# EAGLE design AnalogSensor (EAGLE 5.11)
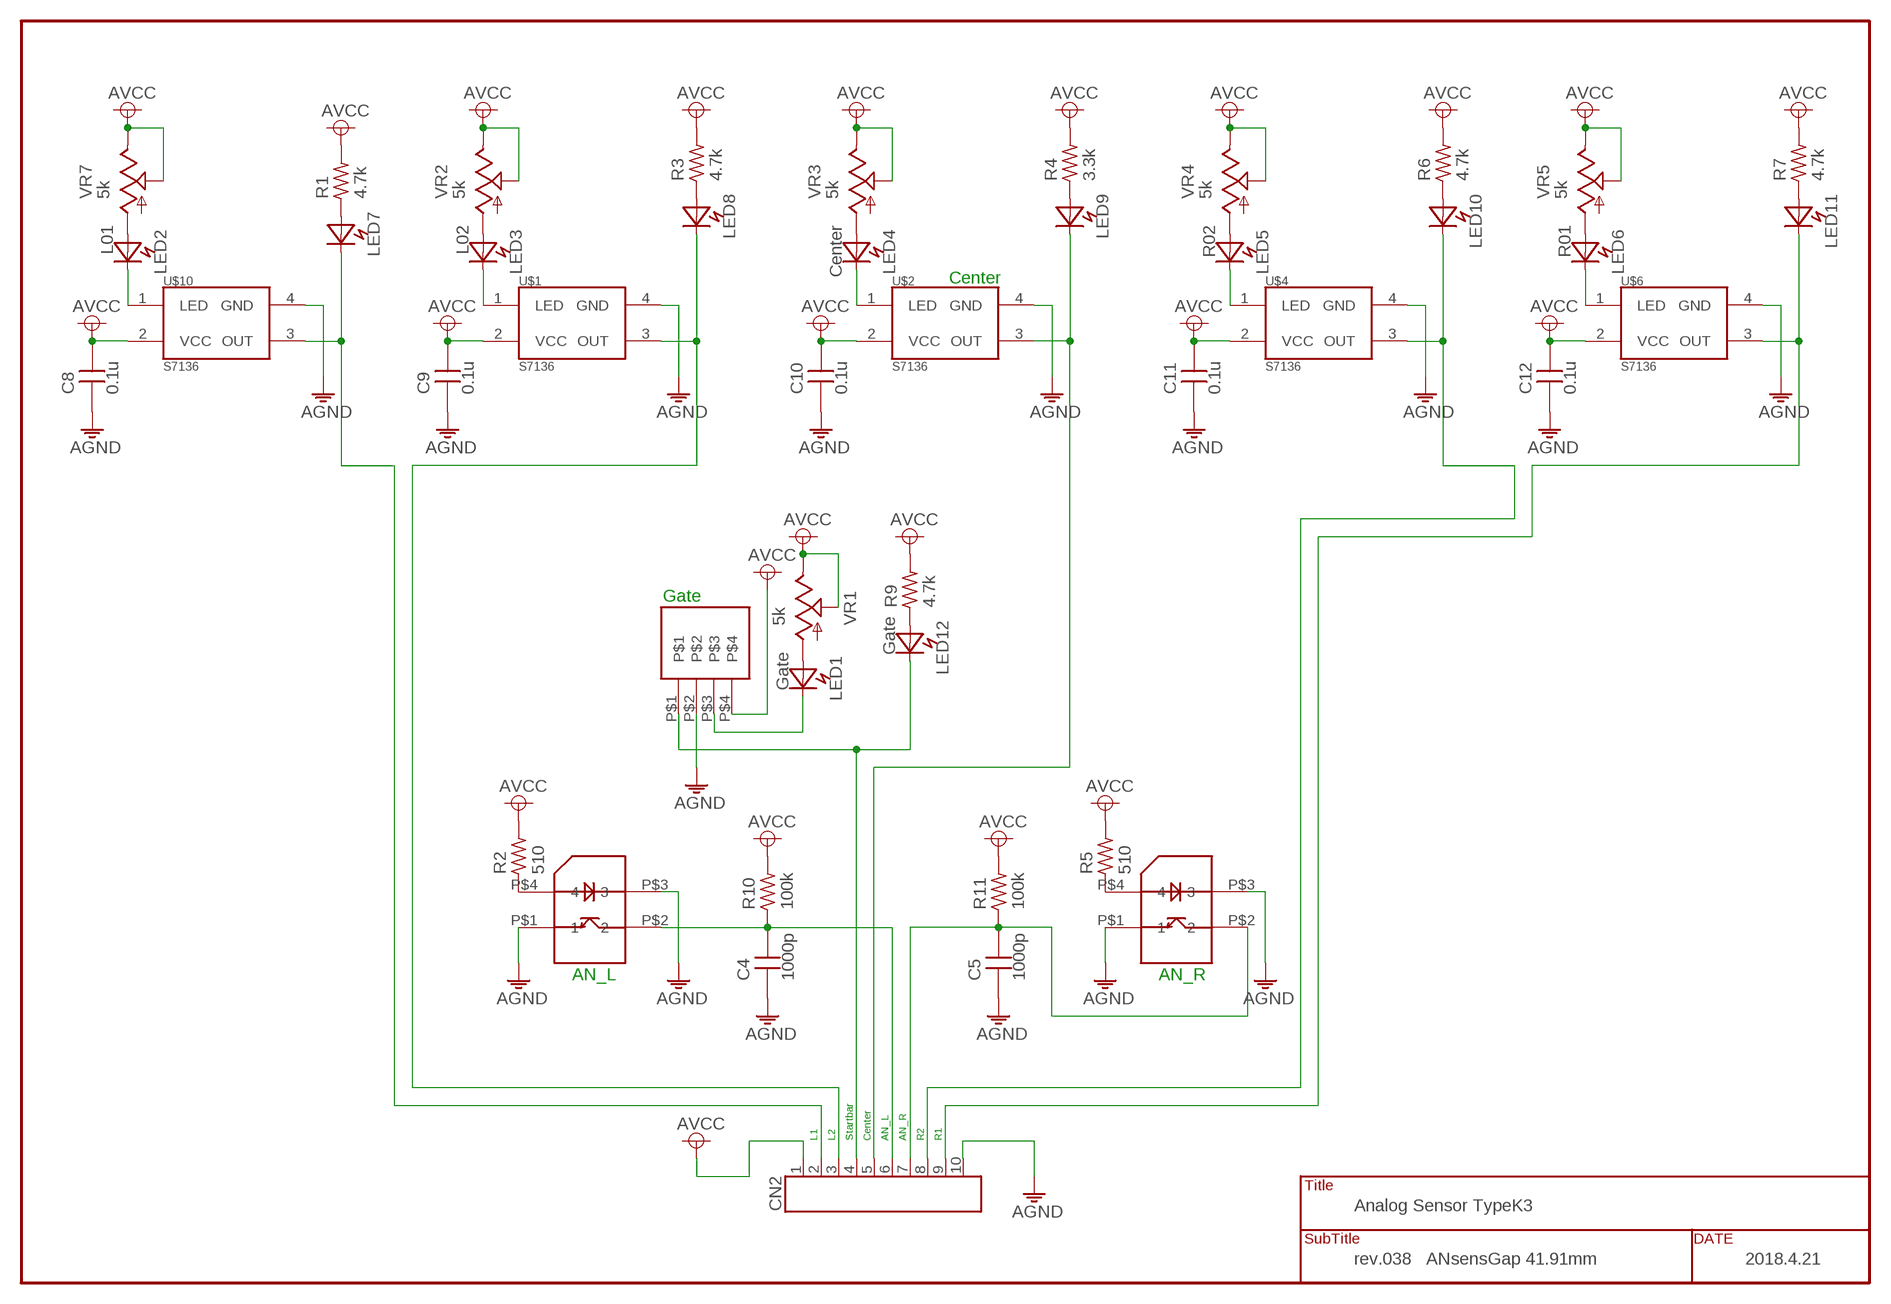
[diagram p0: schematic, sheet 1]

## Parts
C4  1000p  CAP1608RC  [1608]
C5  1000p  CAP1608RC  [1608]
C8  0.1u  CAPSM1608  [C1608]
C9  0.1u  CAPSM1608  [C1608]
C10  0.1u  CAPSM1608  [C1608]
C11  0.1u  CAPSM1608  [C1608]
C12  0.1u  CAPSM1608  [C1608]
CN2  CON_10P-0.8N  [10P-0.8N]
LED1  Gate  LED-0.9  [LED_3MM]
LED2  L01  LED-0.9  [LED_3MM]
LED3  L02  LED-0.9  [LED_3MM]
LED4  Center  LED-0.9  [LED_3MM]
LED5  R02  LED-0.9  [LED_3MM]
LED6  R01  LED-0.9  [LED_3MM]
LED7  LED-1608C  [LED_1608C]
LED8  LED-1608C  [LED_1608C]
LED9  LED-1608C  [LED_1608C]
LED10  LED-1608C  [LED_1608C]
LED11  LED-1608C  [LED_1608C]
LED12  Gate  LED-1608C  [LED_1608C]
R1  4.7k  R1608C  [C1608C]
R2  510  R1608RC  [1608]
R3  4.7k  R1608C  [C1608C]
R4  3.3k  R1608C  [C1608C]
R5  510  R1608RC  [1608]
R6  4.7k  R1608C  [C1608C]
R7  4.7k  R1608C  [C1608C]
R9  4.7k  R1608C  [C1608C]
R10  100k  R1608RC  [1608]
R11  100k  R1608RC  [1608]
U$1  S7136  S7136-0.9  [S7136]
U$2  S7136  S7136-0.9  [S7136]
U$3  GP2S700HCP  GP2S700HCP-SMD  [GP2S700HCP]
U$4  S7136  S7136-0.9  [S7136]
U$6  S7136  S7136-0.9  [S7136]
U$7  GP2S700HCP  GP2S700HCP-SMD  [GP2S700HCP]
U$10  S7136  S7136-0.9  [S7136]
U$15  S6846-SMD  [S6846-SMD]
VR1  5k  POTSMD  [ST-4EB]
VR2  5k  POTSMD  [ST-4EB]
VR3  5k  POTSMD  [ST-4EB]
VR4  5k  POTSMD  [ST-4EB]
VR5  5k  POTSMD  [ST-4EB]
VR7  5k  POTSMD  [ST-4EB]

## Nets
AGND: C4.1 C5.1 C8.1 C9.1 C10.1 C11.1 C12.1 CN2.10 U$1.4(GND) U$2.4(GND) U$3.P$1 U$3.P$3 U$4.4(GND) U$6.4(GND) U$7.P$1 U$7.P$3 U$10.4(GND) U$15.P$2
AN_L: C4.2 CN2.6 R10.1 U$7.P$2
AN_R: C5.2 CN2.7 R11.1 U$3.P$2
AVCC: C8.2 C9.2 C10.2 C11.2 C12.2 CN2.1 R1.2 R2.2 R3.2 R4.2 R5.2 R6.2 R7.2 R9.2 R10.2 R11.2 U$1.2(VCC) U$2.2(VCC) U$4.2(VCC) U$6.2(VCC) U$10.2(VCC) U$15.P$4 VR1.P$2(S) VR1.P$3(E) VR2.P$2(S) VR2.P$3(E) VR3.P$2(S) VR3.P$3(E) VR4.P$2(S) VR4.P$3(E) VR5.P$2(S) VR5.P$3(E) VR7.P$2(S) VR7.P$3(E)
CENTER: CN2.5 LED9.K U$2.3(OUT)
L1: CN2.2 LED7.K U$10.3(OUT)
L2: CN2.3 LED8.K U$1.3(OUT)
N$1: LED3.K U$1.1(LED)
N$2: LED1.A VR1.P$1(A)
N$3: LED3.A VR2.P$1(A)
N$4: R2.1 U$7.P$4
N$5: R5.1 U$3.P$4
N$7: LED4.K U$2.1(LED)
N$11: LED7.A R1.1
N$12: LED8.A R3.1
N$13: LED4.A VR3.P$1(A)
N$14: LED9.A R4.1
N$15: LED1.K U$15.P$3
N$17: LED10.A R6.1
N$18: LED11.A R7.1
N$19: LED5.K U$4.1(LED)
N$20: LED2.K U$10.1(LED)
N$21: LED12.A R9.1
N$23: LED2.A VR7.P$1(A)
N$24: LED5.A VR4.P$1(A)
N$27: LED6.K U$6.1(LED)
N$30: LED6.A VR5.P$1(A)
R1: CN2.9 LED11.K U$6.3(OUT)
R2: CN2.8 LED10.K U$4.3(OUT)
STARTBAR: CN2.4 LED12.K U$15.P$1

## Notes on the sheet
- Center
- Gate
- AN_L | AN_R
- L1 | L2 | Startbar | Center | AN_L | AN_R | R2 | R1
- Analog Sensor TypeK3
- rev.038   ANsensGap 41.91mm | 2018.4.21

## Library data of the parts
C4 C5 C8-C12 = _mylib02:CAP: Non polar capacitor
CN2 = _mylib02:CON_10P: 10P Molex Connector
LED1-LED12 = _mylib02:LED: 3mm LED
R1-R7 R9-R11 = _mylib02:R: General Resiter 1/8W 1/4W 1/2W V/H
U$1 U$2 U$4 U$6 U$10 = _mylib02:S7136
U$3 U$7 = _mylib02:GP2S700HCP
U$15 = _mylib02:S6846
VR1-VR5 VR7 = _mylib02:POT: Volume Trimmer Resister

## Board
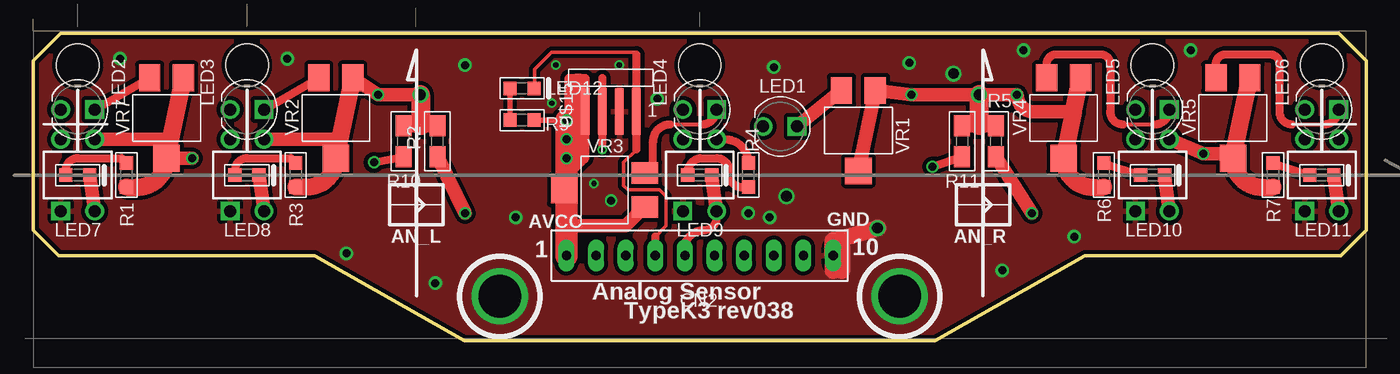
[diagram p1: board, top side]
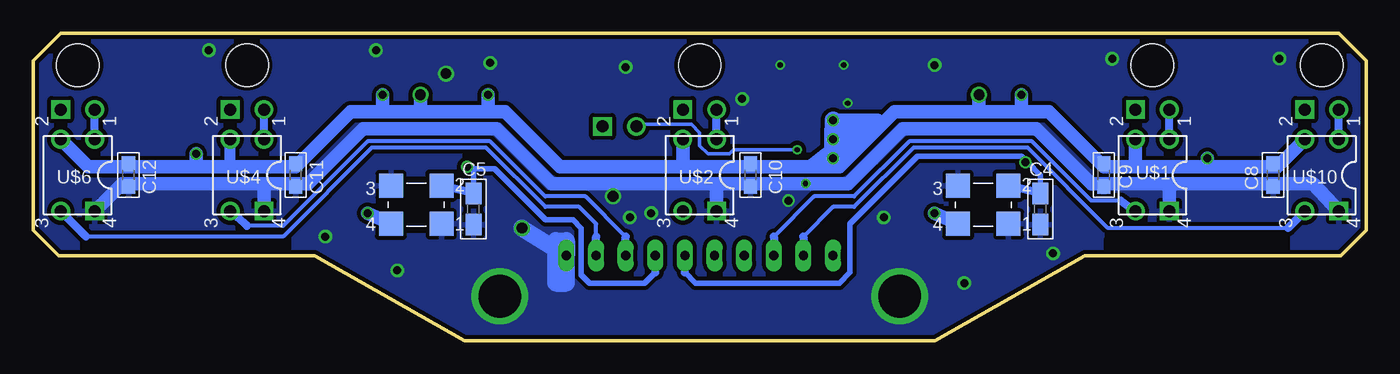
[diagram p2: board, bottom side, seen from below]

Size 100.01 x 23.04 mm. Coordinates in mm from the lower left corner, seen from the top.
Outline: 1.91,6.37 21.11,6.37 32.35,0 67.66,0 78.9,6.37 98.11,6.37 100.01,8.28 100.01,20.98 97.95,23.04 2.06,23.04 0,20.98 0,8.28 1.91,6.37
Copper layers (1*16): Top 0.035mm / dielectric 1.5mm / Bottom 0.035mm
Design rules "Fusion_eagle_rule_v1.1": minimum track width 6mil, minimum drill 12mil, track to track 6mil, track to pad 6mil, pad to pad 6mil, via to via 6mil, smd to smd 0mil, copper to edge 10mil, drill to drill 10mil, minimum pad ring 10mil, minimum via ring 6mil, stop-mask expansion 2mil, vias tented up to drill 100mil, thermal gap 10mil
Holes 3.2 mm at 3.33,20.66 16.03,20.66 50.01,20.66 83.98,20.66 96.68,20.66
tRestrict: area 49.7,9.5 to 49.8,9.9; area 48.6,8.6 to 48.9,8.8
bRestrict: area 6,7 to 6.4,7.6; area 81,7 to 81.3,7.3; area 18.7,7 to 19.4,7.6; area 95.9,7 to 96.2,7.3

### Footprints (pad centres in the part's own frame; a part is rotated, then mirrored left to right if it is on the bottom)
1608 = smd 1.6 x 1.2: 1 -1.167,0; 2 1.167,0
C1608 = smd 1.1 x 1: 1 -0.85,0; 2 0.85,0
10P-0.8N = drill 0.7 pad 1.016 long: 1 -10.001,0; 2 -7.779,0; 3 -5.556,0; 4 -3.334,0; 5 -1.111,0; 6 1.111,0; 7 3.334,0; 8 5.556,0; 9 7.779,0; 10 10.001,0
LED_3MM = drill 0.9 square: A -1.27,0 | drill 0.9 round: K 1.27,0
LED_1608C = smd 1 x 1: A -0.9,0; K 0.9,0
C1608C = smd 1 x 1: 1 -0.9,0; 2 0.9,0
S7136 = drill 0.9 round: 1 -1.27,-2.699; 2 1.27,-2.699; 3 1.27,2.699 | drill 0.9 square: 4 -1.27,2.699
GP2S700HCP = smd 1.8 x 1.8: P$1 -1.9,1.44; P$2 -1.9,-1.44; P$3 1.9,-1.44; P$4 1.9,1.44
S6846-SMD = smd 0.635 x 3.5: P$1 -1.905,0; P$2 -0.635,0; P$3 0.635,0; P$4 1.905,0
ST-4EB = smd 1.6 x 2: P$1 1.27,-2.857; P$3 -1.27,-2.857 | smd 2 x 2: P$2 0,3.175

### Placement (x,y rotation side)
C4  24.45,9.87 90 bottom
C5  66.99,9.87 90 bottom
C8  6.98,12.41 90 bottom
C9  19.69,12.41 90 bottom
C10  46.2,12.41 90 bottom
C11  80.33,12.41 90 bottom
C12  92.87,12.41 90 bottom
CN2  50.01,6.37 0 top
LED1  56.04,16.06 180 top
LED2  3.33,17.33 180 top
LED3  16.03,17.33 180 top
LED4  50.01,17.33 180 top
LED5  83.98,17.33 180 top
LED6  96.68,17.33 180 top
LED7  3.33,12.41 0 top
LED8  16.03,12.41 0 top
LED9  50.01,12.41 0 top
LED10  83.98,12.41 0 top
LED11  96.68,12.41 0 top
LED12  36.67,18.92 0 top
R1  6.98,12.41 270 top
R2  30.32,14.95 90 top
R3  19.69,12.41 270 top
R4  53.66,12.41 90 top
R5  72.23,14.95 90 top
R6  80.33,12.41 270 top
R7  93.03,12.41 270 top
R9  36.67,16.53 0 top
R10  27.78,14.95 90 top
R11  69.69,14.95 90 top
U$1  16.03,12.41 180 bottom
U$2  50.01,12.41 180 bottom
U$3  71.28,10.18 180 bottom
U$4  83.98,12.41 180 bottom
U$6  96.68,12.41 180 bottom
U$7  28.73,10.18 180 bottom
U$10  3.33,12.41 180 bottom
U$15  43.34,17.17 180 top
VR1  61.91,15.9 180 top
VR2  22.7,16.85 180 top
VR3  43.02,11.3 90 top
VR4  77.31,16.85 180 top
VR5  90.01,16.85 180 top
VR7  10,16.85 180 top

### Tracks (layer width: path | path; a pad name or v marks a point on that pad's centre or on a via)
AGND  (via drill 0.4, 0.6, 0.6 pad 1.02, 0.8 pad 1.02, 3.2)
  Top 0.61: 60.64,7.33 60.8,7.33 CN2.10
  Top 1.27: CN2.10 60.01,5.9 | CN2.10 60.01,7.49 v63.34,8.44 | CN2.10 60.01,5.26 | 60.64,7.33 60.64,5.26
  Bottom 0.406: 19.69,11.77 C9.1
  Bottom 0.61: 46.2,11.77 C10.1 | 92.87,11.77 C12.1 | 6.99,11.77 C8.1
  Bottom 1.016: U$10.4 3.97,11.77 6.99,11.77 14.76,11.77 | 14.76,11.77 19.69,11.77 20.64,11.77 24.77,15.9 34.77,15.9 38.89,11.77 46.2,11.77 48.74,11.77 | 82.71,11.77 92.87,11.77 93.35,11.77 U$6.4 | 14.76,11.77 U$1.4 | 48.74,11.77 U$2.4 | 48.74,11.77 61.12,11.77 65.25,15.9 75.25,15.9 79.38,11.77 82.71,11.77 | 82.71,11.77 U$4.4
  Bottom 1.27: CN2.10 v63.34,8.44 | CN2.10 60.01,4.31 60.8,4.31 60.8,7.49 60.01,7.49 CN2.10
  other vias: 56.52,10.82 35.01,3.32 65.01,3.32 55.56,20.5 69.06,20.03 65.72,20.82 74.3,21.77 46.83,18.12 6.51,21.14 55.25,9.23 86.84,21.77 19.05,21.14 32.38,20.66 53.66,9.55 43.34,10.5 36.2,9.23 39.21,20.66 38.89,17.8 43.97,20.66 78.11,7.8 72.71,5.26 23.5,6.53 30.16,4.31 42.07,11.77
  pour Bottom (isolate 0.305): -0.32,23.2 100.33,23.2 100.33,0.18 -0.32,0.18
  pour Top (isolate 0.305): -0.16,23.2 100.17,23.2 100.17,0.18 -0.16,0.18
AN_L  (via drill 0.6)
  Top 0.61: v25.56,13.36 R10.1
  Bottom 0.406: 51.12,5.1 50.32,4.31 39.53,4.31 38.74,5.1 38.74,8.76 33.66,13.84 25.88,13.84 25.72,13.68 25.4,13.36 | 25.4,13.36 24.45,12.41 C4.2 | 25.4,13.36 v25.56,13.36
  Bottom 0.61: 51.12,5.1 CN2.6 | C4.2 U$7.P$2
AN_R  (via drill 0.6)
  Top 0.61: v67.47,13.04 R11.1
  Bottom 0.406: 53.34,5.1 54.13,4.31 58.26,4.31 58.9,4.95 58.9,8.44 59.53,9.07 61.6,9.07 65.41,12.88 66.2,12.88 66.99,12.88 | 66.99,12.88 C5.2 | 66.99,12.88 v67.47,13.04
  Bottom 0.61: 53.34,5.1 CN2.7 | C5.2 U$3.P$2
AVCC  (via drill 0.6, 0.8)
  Top 0.406: v40.01,16.53 R9.2
  Top 0.61: R4.2 arc90 51.86,15.11 U$2.2 | 41.43,16.53 41.43,13.68 41.12,13.36 | v40.01,13.68 40.16,12.41 | 40.64,16.53 41.43,16.53 | 40.48,16.53 40.64,16.53 | 41.43,16.53 U$15.P$4 41.43,19.71 41.12,19.71 | 40.64,19.71 40.16,19.71 40.16,12.41 | 40.16,12.41 41.12,13.36 | 41.12,13.36 41.12,19.71 | 41.12,19.71 40.64,19.71 | 40.64,19.71 40.64,16.53
  Top 1.016: R2.2 29.07,16.11 R10.2 | R11.2 70.97,16.11 71.6,16.11 R5.2 | 40.01,11.3 VR3.P$2 | VR3.P$3 44.45,8.6 40.01,8.6 | VR2.P$3 v25.88,18.44 v29.05,18.44 | VR7.P$2 v11.91,13.68 | 78.04,17.15 75.11,17.15 arc-90 v73.82,18.44 v70.96,18.44 v65.88,18.44 VR1.P$3 VR1.P$2 | VR5.P$2 89.69,13.99 v87.79,13.99 U$4.2 | U$10.2 10.16,15.11 arc-90 10.32,14.95 | U$1.2 22.86,15.11 arc-90 23.02,14.95 | v40.01,16.53 40.48,16.53
  Top 1.27: VR7.P$3 VR7.P$2 arc-90 7.83,11.51 R1.2 | VR2.P$3 VR2.P$2 arc-90 20.53,11.51 R3.2 | VR4.P$3 78.45,19.1 78.04,17.15 VR4.P$2 arc90 79.48,11.51 R6.2 | VR5.P$3 VR5.P$2 arc90 92.18,11.51 R7.2
  Top 1.422: v29.05,18.44 29.07,16.11 | v70.96,18.44 70.97,16.11
  Top 1.676: v40.01,16.53 v40.01,15.11 v40.01,13.68 40.01,11.3 40.01,8.6 CN2.1
  Bottom 0.254: 79.53,13.84 77.63,15.58
  Bottom 0.61: 6.99,13.04 arc-90 6.99,13.04 | 6.99,13.04 C8.2
  Bottom 0.813: 85.25,13.04 U$4.2
  Bottom 1.016: 40.01,13.04 v40.01,13.68 | 40.01,13.04 41.75,13.04 | 41.75,13.04 46.2,13.04 | 46.2,13.04 51.28,13.04 | 51.28,13.04 60.48,13.04 64.61,17.17 65.88,17.17 | 65.88,17.17 70.96,17.17 | 80.33,13.04 85.25,13.04 87.79,13.04 | 87.79,13.04 92.87,13.04 | 92.87,13.04 95.89,13.04 U$6.2 | 40.01,13.04 39.53,13.04 35.56,17.01 | 35.56,17.01 | 35.56,17.01 35.4,17.17 29.05,17.17 | 25.88,17.17 23.81,17.17 19.69,13.04 | 25.88,17.17 29.05,17.17 | 6.99,13.04 6.67,13.04 U$10.2 | 11.91,13.04 6.99,13.04 | 11.91,13.04 17.3,13.04 | 17.3,13.04 19.69,13.04 | 19.69,13.04 | 6.99,13.04 | 19.69,13.04 C9.2 | 17.3,13.04 U$1.2 | 51.28,13.04 U$2.2 | 80.33,13.04 C11.2 | 92.87,13.04 C12.2 | 46.2,13.04 C10.2 | 29.05,17.17 v29.05,18.44 | 70.96,17.17 v70.96,18.44 | 70.96,17.17 73.82,17.17 | 73.82,17.17 76.2,17.17 79.53,13.84 80.33,13.04 | 25.88,17.17 v25.88,18.44 | v11.91,13.68 11.91,13.04 | 73.82,17.17 v73.82,18.44 | 87.79,13.04 v87.79,13.99 | 65.88,17.17 v65.88,18.44 | v40.01,15.11 39.85,14.95 | 39.85,14.95 39.21,14.31 38.26,14.95 39.85,14.95 | 41.75,13.04 40.01,14.38 | 40.01,15.94 37.62,15.58 36.67,16.53 39.85,16.53
  Bottom 1.27: v40.01,13.68 40.01,14.38 v40.01,15.11 40.01,15.94 v40.01,16.53
CENTER
  Top 0.61: U$2.3 51.28,9.23 arc-90 50.32,8.28 arc106 CN2.5
  Top 1.016: U$2.3 LED9.K
L1
  Top 1.016: U$10.3 LED7.K
  Bottom 0.305: 5.87,8.44 19.37,8.44 25.4,14.47 33.97,14.47 38.42,10.03 40.01,10.03 42.23,7.8
  Bottom 0.61: U$10.3 5.87,8.44 | 42.23,7.8 CN2.2
L2
  Top 1.016: U$1.3 LED8.K
  Bottom 0.305: 18.42,10.5 20.64,10.5 25.08,14.95 34.29,14.95 38.42,10.82 41.43,10.82 44.45,7.8
  Bottom 0.61: U$1.3 18.42,10.5 | 44.45,7.8 CN2.3
N$1
  Bottom 0.61: U$1.1 LED3.K
N$2
  Top 1.016: LED1.A VR1.P$1
N$3
  Top 0.61: LED3.A VR2.P$1
N$4  (via drill 0.6)
  Top 1.016: v32.39,9.55 R2.1
  Bottom 1.016: U$7.P$4 v32.39,9.55
N$5  (via drill 0.6)
  Top 1.016: v74.93,9.55 R5.1
  Bottom 1.016: U$3.P$4 v74.93,9.55
N$7
  Bottom 0.61: U$2.1 LED4.K
N$11
  Top 0.61: R1.1 6.62,13.68 3.33,13.68 arc90 2.43,12.78 LED7.A
N$12
  Top 0.61: R3.1 19.32,13.68 16.03,13.68 arc90 15.13,12.78 LED8.A
N$13
  Top 0.305: 47.78,16.22 50.17,16.22
  Top 0.61: 50.17,16.22 arc90 LED4.A | 47.78,16.22 arc90 46.51,14.95 46.51,13.04 arc-90 46.04,12.57 VR3.P$1
N$14
  Top 0.61: R4.1 53.13,11.51 arc-90 52.23,12.41 52.23,12.72 arc90 51.28,13.68 50.06,13.68 arc90 LED9.A
N$15  (via drill 0.4)
  Top 0.61: v42.7,14.31 U$15.P$3 42.7,19.71
  Bottom 0.254: LED1.K 54.29,16.22 50.64,16.22 50.01,15.58 50.01,14.63 49.37,13.99 47.78,13.99 47.47,14.31 v42.7,14.31
N$17
  Top 0.61: R6.1 LED10.A
N$18
  Top 0.61: R7.1 LED11.A
N$19
  Bottom 0.61: U$4.1 LED5.K
N$20
  Bottom 0.61: U$10.1 LED2.K
N$21
  Top 0.406: R9.1 LED12.A
N$23
  Top 0.61: LED2.A VR7.P$1
N$24
  Top 0.305: 81.76,16.22 84.14,16.22
  Top 0.61: 84.14,16.22 arc90 LED5.A | 81.76,16.22 arc-90 80.8,17.17 80.8,20.66 arc90 80.17,21.46 76.68,21.46 arc90 76.04,20.66 VR4.P$1
N$27
  Bottom 0.61: U$6.1 LED6.K
N$30
  Top 0.305: 94.46,16.22 96.84,16.22
  Top 0.61: 96.84,16.22 arc90 LED6.A | 94.46,16.22 arc-90 93.5,17.17 93.5,20.66 arc90 92.87,21.46 89.38,21.46 arc90 88.74,20.66 VR5.P$1
R1
  Top 1.016: U$6.3 LED11.K
  Bottom 0.305: 96.04,7.8 81.28,7.8 74.61,14.47 66.04,14.47 61.6,10.03 59.06,10.03 57.79,8.76 57.79,7.8
  Bottom 0.61: 96.04,7.8 U$6.3 | CN2.9 57.79,7.8
R2
  Top 1.016: U$4.3 LED10.K
  Bottom 0.305: 55.56,7.8 58.58,10.82 61.6,10.82 65.72,14.95 74.93,14.95 81.28,8.6 83.98,8.6
  Bottom 0.61: 83.98,8.6 U$4.3 | CN2.8 55.56,7.8
STARTBAR
  Top 0.254: 45.24,14.31 44.29,13.36 44.29,11.61 44.61,11.3 46.99,11.3 47.47,10.82 47.47,8.6 46.67,7.8 | CN2.4 | LED12.K 37.62,19.07 37.62,20.34 38.89,21.61 45.24,21.61 45.24,21.46
  Top 0.61: 45.24,14.31 U$15.P$1 45.24,21.46 | CN2.4 46.67,7.8

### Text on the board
tPlace: AVCC | GND | AN_L | AN_R | 1 | 10 | Analog Sensor | TypeK3 rev038
bValues: GP2S700HCP | GP2S700HCP
tDocu: 46.6725 | 33.9725 | 21.2725 | 0 | 50.0062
